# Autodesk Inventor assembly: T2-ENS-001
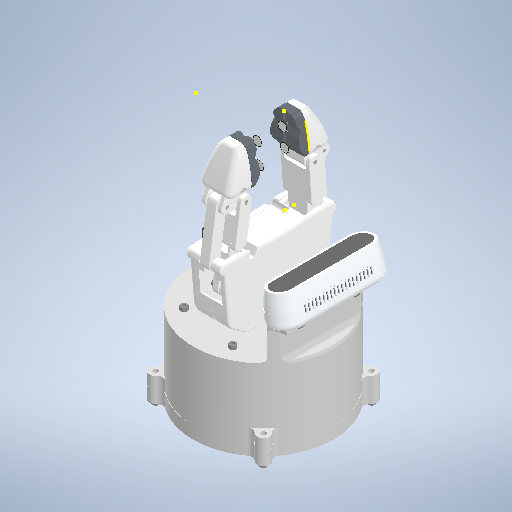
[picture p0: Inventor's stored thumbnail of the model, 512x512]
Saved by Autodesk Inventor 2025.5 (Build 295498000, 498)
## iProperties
Created: 2026-10
Part Number: T2-ENS-001
Document SubType Name: Assembly
Designer: Luis MuÃ±oz
Project: TESIS 2 - Plataforma mecatrÃ³nica preventiva desacoplada
Description: Sistema de gripper instrumentado para JACO2
Author: Luis M
Title: Sistema de gripper instrumentado para JACO2
Revision Number: 00
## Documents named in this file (6)
- C:\Users\Luis M\Desktop\TESIS\CAD_TESIS_ORGANIZADO\01_ENSAMBLES\SISTEMA_GRIPPER_INSTRUMENTADO_JACO2.iam
- C:\Users\Luis M\Desktop\TESIS\CAD_TESIS_ORGANIZADO\01_ENSAMBLES\MODULO_ELECTRONICA_PERCEPCION_RGBD.iam
- C:\Users\Luis M\Desktop\TESIS\CAD_TESIS_ORGANIZADO\01_ENSAMBLES\GRIPPER_ADAPTATIVO_INSTRUMENTADO.iam
- C:\Users\Luis M\Desktop\TESIS\CAD_TESIS_ORGANIZADO\02_PIEZAS\COMERCIALES_COMPARTIDAS\TORNILLO_HEX_INTERIOR_M3X8.ipt
- C:\Users\Luis M\Desktop\TESIS\CAD_TESIS_ORGANIZADO\02_PIEZAS\COMERCIALES_COMPARTIDAS\TORNILLO_HEX_INTERIOR_M3X16.ipt
- C:\Users\Luis M\Desktop\TESIS\CAD_TESIS_ORGANIZADO\02_PIEZAS\COMERCIALES_COMPARTIDAS\FSR_DF9-40.iam
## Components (15 placed, 5 different names)
1. MODULO_ELECTRONICA_PERCEPCION_RGBD:1 [sub-assembly]
2. GRIPPER_ADAPTATIVO_INSTRUMENTADO:1 [sub-assembly] — Coincidencia:1, Coincidencia:2, Coincidencia:3, Coincidencia:18, Coincidencia:19, Coincidencia:20, Coincidencia:21
3. TORNILLO_HEX_INTERIOR_M3X8:1 — Nivelación:2, Coincidencia:9
4. TORNILLO_HEX_INTERIOR_M3X8:2 — Nivelación:3, Coincidencia:5
5. TORNILLO_HEX_INTERIOR_M3X8:3 — Nivelación:1, Nivelación:2, Coincidencia:4, Coincidencia:6
6. TORNILLO_HEX_INTERIOR_M3X8:4 — Nivelación:1, Nivelación:3, Nivelación:4, Coincidencia:7
7. TORNILLO_HEX_INTERIOR_M3X8:5 — Nivelación:4, Coincidencia:8
8. hex_socket_cylindrical_head_M3x16:1 — Nivelación:6, Coincidencia:22
9. hex_socket_cylindrical_head_M3x16:2 — Nivelación:7, Coincidencia:24, Coincidencia:26
10. hex_socket_cylindrical_head_M3x16:3 — Nivelación:5, Nivelación:6, Nivelación:7, Coincidencia:23
11. hex_socket_cylindrical_head_M3x16:4 — Nivelación:5, Coincidencia:25
12. FSR_DF9-40:1 [sub-assembly] — Coincidencia:19
13. FSR_DF9-40:2 [sub-assembly] — Coincidencia:18
14. FSR_DF9-40:3 [sub-assembly] — Coincidencia:21
15. FSR_DF9-40:4 [sub-assembly] — Coincidencia:20
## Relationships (25: Mate 18, Flush 7)
- Coincidencia:1 [Mate]: GRIPPER_ADAPTATIVO_INSTRUMENTADO:1
- Coincidencia:2 [Mate]: GRIPPER_ADAPTATIVO_INSTRUMENTADO:1
- Coincidencia:3 [Mate]: GRIPPER_ADAPTATIVO_INSTRUMENTADO:1
- Nivelación:1 [Flush]: TORNILLO_HEX_INTERIOR_M3X8:3 ↔ TORNILLO_HEX_INTERIOR_M3X8:4
- Nivelación:2 [Flush]: TORNILLO_HEX_INTERIOR_M3X8:1 ↔ TORNILLO_HEX_INTERIOR_M3X8:3
- Nivelación:3 [Flush]: TORNILLO_HEX_INTERIOR_M3X8:2 ↔ TORNILLO_HEX_INTERIOR_M3X8:4
- Nivelación:4 [Flush]: TORNILLO_HEX_INTERIOR_M3X8:4 ↔ TORNILLO_HEX_INTERIOR_M3X8:5
- Coincidencia:4 [Mate]: TORNILLO_HEX_INTERIOR_M3X8:3
- Coincidencia:5 [Mate]: TORNILLO_HEX_INTERIOR_M3X8:2
- Coincidencia:6 [Mate]: TORNILLO_HEX_INTERIOR_M3X8:3
- Coincidencia:7 [Mate]: TORNILLO_HEX_INTERIOR_M3X8:4
- Coincidencia:8 [Mate]: TORNILLO_HEX_INTERIOR_M3X8:5
- Coincidencia:9 [Mate]: TORNILLO_HEX_INTERIOR_M3X8:1
- Nivelación:5 [Flush]: hex_socket_cylindrical_head_M3x16:3 ↔ hex_socket_cylindrical_head_M3x16:4
- Nivelación:6 [Flush]: hex_socket_cylindrical_head_M3x16:1 ↔ hex_socket_cylindrical_head_M3x16:3
- Nivelación:7 [Flush]: hex_socket_cylindrical_head_M3x16:2 ↔ hex_socket_cylindrical_head_M3x16:3
- Coincidencia:18 [Mate]: GRIPPER_ADAPTATIVO_INSTRUMENTADO:1 ↔ FSR_DF9-40:2
- Coincidencia:19 [Mate]: GRIPPER_ADAPTATIVO_INSTRUMENTADO:1 ↔ FSR_DF9-40:1
- Coincidencia:20 [Mate]: GRIPPER_ADAPTATIVO_INSTRUMENTADO:1 ↔ FSR_DF9-40:4
- Coincidencia:21 [Mate]: GRIPPER_ADAPTATIVO_INSTRUMENTADO:1 ↔ FSR_DF9-40:3
- Coincidencia:22 [Mate]: hex_socket_cylindrical_head_M3x16:1
- Coincidencia:23 [Mate]: hex_socket_cylindrical_head_M3x16:3
- Coincidencia:24 [Mate]: hex_socket_cylindrical_head_M3x16:2
- Coincidencia:25 [Mate]: hex_socket_cylindrical_head_M3x16:4
- Coincidencia:26 [Mate]: hex_socket_cylindrical_head_M3x16:2
